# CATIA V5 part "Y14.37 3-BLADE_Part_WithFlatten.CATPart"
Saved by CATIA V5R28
Part number: ASME Y14.37 3-Blade Example
Bounding box of the stored display mesh (mm): x -269.801 to 271.708, y 0 to 127, z -180.306 to 271.736
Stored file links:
  C:\Users\jvl2147\Documents\ASME Y14.37\PartExamples\Y14.37 3-BLADE_Part_WithFlatten.CATPart
  C:\Program Files\Dassault Systemes\B28SP3PRALL\win_b64\startup\composites\CompositesCatalog.CATMaterial
  E:\ASME Y14.37\ASME Y-14.37_COMPOSITES.CATMaterial
  C:\Program Files\Dassault Systemes\B28SP3PRALL\win_b64\startup\composites\LaminateColors.txt
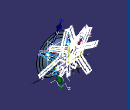
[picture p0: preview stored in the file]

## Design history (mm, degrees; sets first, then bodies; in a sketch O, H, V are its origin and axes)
CompParametersFeature1 "CATCoParametersFeatName": Value 0, Value 45, Value -45, Value 90
CompStacking1 "Stacking"
AxisSystem1 "Local Axis System": origin (0, 0, 0), X (-0.866, 0, 0.5), Y (0.5, 0, 0.866), Z (0, 1, 0)
CompReviewTools1 "Review tools"
CompEOPGroupFeature1 "CATCoEOPGroupFeatName"
Set1 "Construction Geometry (REF)"
  Sketch1 on xy-plane, origin (0, 0, 0), H (1, 0, 0), V (0, 1, 0)
    point P1 (-167.1288, 0)
    line L1 (-167.1288, 0) -> (-142.3543, 0)
    line L2 (-123.3692, 8.8246) -> (-66.4127, 76.365)
    arc A1 centre (-42.4512, 56.1584) radius 31.3442 from (-66.4127, 76.365) to (-29.9974, 84.9223) cw
    arc A2 centre (-21.0644, 105.5542) radius 22.4828 from (-29.9974, 84.9223) to (-21.0644, 83.0715) ccw
    line L3 (-21.0644, 83.0715) -> (0, 83.0715)
    point P7 (0, 83.0715)
    axis line L4 (0, 104.2142) -> (0, -35.51)
    point P8 (0, 104.2142)
    arc A3 centre (-142.3543, 24.8346) radius 24.8346 from (-142.3543, 0) to (-123.3692, 8.8246) ccw
    radius A3 = 24.8346
    coincidence: P1 H, P7 V, P8 V
    horizontal: L1 H, L3 H
    tangency: A1 L2, A2 A1, A2 L3, A3 L1, A3 L2
    vertical: L4 V
  Set2 "Engineering Geometry"
    Revol1: Element1 Sketch1, Angle1 360
  Plane1: type Offset, RefPlane yz-plane, Offset 12.7
  Plane2: type Offset, RefPlane yz-plane, Offset 12.7, reversed
  Plane3: type Angle, RefPlane yz-plane, Direction Y axis, Angle 60
  Plane4: type Angle, RefPlane Plane3, Direction Y axis, Angle 60
  MultiSel1
  Plane5: type Offset, RefPlane Plane4, Offset 12.7
  Intersect1: ToIntersect1 {inverselocal InverseElem Plane5}, ToIntersect2 Revol1
  Intersect2: ToIntersect1 {inverselocal InverseElem Plane6}, ToIntersect2 Revol1
  Plane6: type Offset, RefPlane Plane4, Offset 12.7, reversed
  Plane7: type Offset, RefPlane Plane3, Offset 12.7, reversed
  Intersect3: ToIntersect1 {inverselocal InverseElem Plane7}, ToIntersect2 Revol1
  Intersect4: ToIntersect1 {inverselocal InverseElem Plane8}, ToIntersect2 Revol1
  Plane8: type Offset, RefPlane Plane3, Offset 12.7
  Corner1: Element1 Intersect4, Element2 {intersect ToIntersect1 Plane1, ToIntersect2 Revol1}, Support Revol1, Radius 25.4
  Corner2: Element1 Intersect3, Element2 Intersect2, Support Revol1, Radius 25.4
  Corner3: Element1 {intersect ToIntersect1 Plane2, ToIntersect2 Revol1}, Element2 Intersect1, Support Revol1, Radius 25.4
  Trim1: Trimmed (Intersect2; Corner2; Intersect3)
  Trim2: Trimmed (Intersect4; Corner1; {intersect ToIntersect1 Plane1, ToIntersect2 Revol1})
  Trim3: Trimmed ({intersect ToIntersect1 Plane2, ToIntersect2 Revol1}; Corner3; Intersect1)
  Line1: type PtPt, FirstPoint vertex of Intersect1, SecondPoint vertex of Intersect2, Support Revol1
  Line2: type PtPt, FirstPoint vertex of Intersect3, SecondPoint vertex of Intersect4, Support Revol1
  Line3: type PtPt, FirstPoint vertex of MultiSel1, SecondPoint vertex of MultiSel1, Support Revol1
  CurvePar1: Offset Line1, Support Revol1, Offset2 0, Offset1 5.08
  CurvePar2: Offset Line3, Support Revol1, Offset2 0, Offset1 5.08
  CurvePar3: Offset Line2, Support Revol1, Offset2 0, Offset1 5.08
  Contour1: BaseSurface Revol1, Wires (Trim1; CurvePar1; Trim3; CurvePar2; Trim2; CurvePar3), ExtrapolLength 0.003
  Line4: type PtDir, RefPoint vertex [YZ plane of AxisSystem1 | ZX plane of AxisSystem1 | XY plane of AxisSystem1], Direction zx-plane, Start -55, End 165
  Plane9: type Angle, RefPlane yz-plane, Direction Y axis, Angle 30
  Plane10: type Angle, RefPlane yz-plane, Direction Y axis, Angle -30
  Plane11: type Offset, RefPlane zx-plane, Offset 31
  Set3 "Construction - Rosettes"
    Split1: ToCut Intersect5, Cutting (Intersect1; Intersect2)
    Near1: MultiElement Split1, ReferenceElement Line1
    Split2: ToCut Intersect5, Cutting (Intersect3; Intersect4)
    Near2: MultiElement Split2, ReferenceElement Line2
    Split3: ToCut Intersect5, Cutting ({intersect ToIntersect1 Plane1, ToIntersect2 Revol1}; {intersect ToIntersect1 Plane2, ToIntersect2 Revol1})
    Near3: MultiElement Split3, ReferenceElement Line3
    Point1: type OnCurve, Support Near1, Ratio 0.5
    Point2: type OnCurve, Support Near3, Ratio 0.5
    Point3: type OnCurve, Support Near2, Ratio 0.5
    Line5: type Normal, RefPoint Point2, RefSkin Join1, Start 0, End 25.4
    Line6: type Normal, RefPoint Point3, RefSkin Join1, Start 0, End 25.4
    Line7: type Normal, RefPoint Point1, RefSkin Join1, Start 0, End 25.4
  Point4: (1.8096, 83.0715, -11.204)
  Extract1: ExtractElem edge [face of Revol1 from Sketch1.A2 | face of Revol1 from Sketch1.A1]
Set4 "Engineering Geometry"
  Join1 "Definition Surface": Elements Revol1
  AxisSystem2 "Rosette - A": origin (-90.6458, 31, 52.3344), X (0.5583, 0.7645, -0.3223), Y (-0.5, 0, -0.866), Z (-0.662, 0.6447, 0.3822)
  AxisSystem3 "Rosette - B": origin (0, 31, -104.6688), X (0, 0.7645, 0.6447), Y (1, 0, 0), Z (0, 0.6447, -0.7645)
  AxisSystem4 "Rosette - C": origin (90.6458, 31, 52.3344), X (-0.5583, 0.7645, -0.3223), Y (-0.5, 0, 0.866), Z (0.662, 0.6447, 0.3822)
  Intersect5 "90deg Curve": ToIntersect1 Plane11, ToIntersect2 Join1
  Plane12 "Flatten Plane": type Offset, Offset 127, RefPlane zx-plane
Body1 "-1 BOND ASSEMBLY" (main body)
  Solid1: solid without history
